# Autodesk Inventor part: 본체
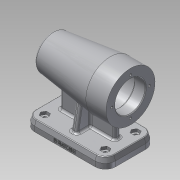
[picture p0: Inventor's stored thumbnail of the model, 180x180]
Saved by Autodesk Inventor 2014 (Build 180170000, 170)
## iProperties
Created: 2017-01
Part Number: 본체
Material: 알루미늄 6061
Document SubType Name: Modeling
Designer: Administrator
Mass: 795.171 g
Surface Area: 661.82 cm^2
Volume: 293.421 cm^3
Density: 2.71 g/cm^3
Appearance: 알루미늄 - 평지
Author: Administrator
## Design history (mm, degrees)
sketch "스케치1"
  geometry: L1 (-56, 35)-(56, 35); L2 (56, 35)-(56, -35); L3 (56, -35)-(-56, -35); L4 (-56, -35)-(-56, 35); L5 (-56, 35)-(56, -35); L6 (56, 35)-(-56, -35); 1 further point
  constraints: 12 end point, 2 midpoint, 2 parallel, 1 horizontal, 1 perpendicular
  dimensions: "d0" = 70 distance of L1.end L2.end; "d1" = 112 distance of L1.start L1.end
extrude "돌출1" new body sketch "스케치1" distance "d2" = 14; taper "d3" = 0 deg
fillet "모깎기1" dims "d4" = 14
chamfer "모따기1" distance "d5" = 7; stored, may be unused: second distance "d6" = 2, angle "d7" = 15 deg
fillet "모깎기2" dims "d8" = 1
sketch "스케치2"
  geometry: L1 (-38, 4)-(38, 4); L2 (38, 4)-(38, -4); L3 (38, -4)-(-38, -4); L4 (-38, -4)-(-38, 4); L5 (-38, 4)-(38, -4); L6 (38, 4)-(-38, -4); L7 (56, 21)-(56, -21) reference; L8 (-56, 21)-(-56, -21) reference; L9 (-4, 23)-(4, 23); L10 (4, 23)-(4, -23); L11 (4, -23)-(-4, -23); L12 (-4, -23)-(-4, 23); L13 (-4, 23)-(4, -23); L14 (4, 23)-(-4, -23); 1 further point
  constraints: 24 end point, 4 midpoint, 4 parallel, 2 horizontal, 2 perpendicular
  dimensions: "d9" = 76 distance of L1.start L1.end; "d12" = 8 distance of L3.end L1.start; "d13" = 8 distance of L9.start L9.end; "d14" = 46 distance of L9.end L10.end
extrude "돌출2" join sketch "스케치2" distance "d15" = 74; taper "d16" = 0 deg
feature "면 기울기1" dims angle "d17" = 10 deg
sketch "스케치3"
  geometry: L1 (56, 74)-(-56, 74); L2 (56, 74)-(56, 108); L3 (56, 108)-(28, 108); L4 (28, 108)-(-52.27, 98.144); L5 (42, 0)-(-42, 0) reference; A1 r 80 centre (24, 74) between (-52.27, 98.144) and (-56, 74); 3 further points
  constraints: 8 end point, 2 midpoint, 2 perpendicular, 2 point on circle, 1 centre point, 1 horizontal, 1 horizontal alignment, 1 vertical alignment
  dimensions: "d18" = 28 distance of L2.end L3.end; "d19" = 80 radius of A1; "d20" = 112 distance of L1.start L1.end; "d21" = 7 deg angle of L3 L4; "d22" = 74 distance between parallel lines of L5 L1; "d23" = 68 diameter of L3 L1
revolve "회전1" sketch "스케치3" stored, may be unused: angle "d24" = 90 deg
sketch "스케치4"
  geometry: L1 (56, 40)-(56, 108) reference; L2 (56, 74)-(41, 74); L3 (41, 74)-(41, 95); L4 (41, 95)-(56, 95); L5 (56, 95)-(56, 74); L6 (41, 74)-(-13, 74); L7 (-13, 74)-(-13, 98); L8 (-13, 98)-(41, 98); L9 (41, 98)-(41, 74); L10 (-13, 74)-(-25, 74); L11 (-25, 74)-(-25, 95); L12 (-25, 95)-(-13, 95); L13 (-13, 95)-(-13, 74); L14 (-25, 74)-(-43, 74); L15 (-43, 74)-(-43, 91.5); L16 (-43, 91.5)-(-25, 91.5); L17 (-25, 91.5)-(-25, 74); L18 (-43, 74)-(-47, 74); L19 (-47, 74)-(-47, 90); L20 (-47, 90)-(-43, 90); L21 (-43, 90)-(-43, 74); L22 (-47, 74)-(-50, 74); L23 (-50, 74)-(-50, 84.5); L24 (-50, 84.5)-(-47, 84.5); L25 (-47, 84.5)-(-47, 74); A1 r 80 centre (24, 74) between (-52.27, 98.144) and (-52.27, 49.856) reference; 1 further point
  constraints: 48 end point, 12 parallel, 6 horizontal, 6 perpendicular, 1 midpoint
  dimensions: "d25" = 15 distance of L3.end L4.end; "d26" = 54 distance of L7.end L8.end; "d27" = 12 distance of L11.end L12.end; "d28" = 18 distance of L15.end L16.end; "d29" = 4 distance of L19.end L20.end; "d30" = 3 distance of L23.end L24.end; "d31" = 42 diameter of L4 L2; "d32" = 48 diameter of L8 L6; "d33" = 42 diameter of L12 L10; "d34" = 35 diameter of L16 L14; "d35" = 32 diameter of L20 L18; "d36" = 21 diameter of L24 L22
revolve "회전2" sketch "스케치4" stored, may be unused: angle "d37" = 90 deg
fillet "모깎기3" dims "d38" = 3
fillet "모깎기4" dims "d39" = 0.3
fillet "모깎기5" dims "d40" = 3
chamfer "모따기2" distance "d41" = 1; stored, may be unused: second distance "d42" = 2, angle "d43" = 15 deg
fillet "모깎기6" dims "d44" = 3
fillet "모깎기7" dims "d45" = 3, "d46" = 3
sketch "스케치6"
  geometry: C1 r 22 at (0, 0) reference; A1 r 26 centre (0, 0) between (26, 0) and (0, 26); 3 further points
  constraints: 4 point on circle, 1 centre point
  dimensions: "d47" = 52 diameter of A1
hole "구멍1" sketch "스케치6" at (26, 0), (0, 26), (0, -26), (-26, 0) diameter "d48" = 3.242; stored, may be unused: countersink angle "d52" = 90 deg, drill point angle "d54" = 118 deg; dims "d49" = 8, "d50" = 4, "d51" = 2, "d53" = 11
fillet "모깎기8" dims "d55" = 3
sketch "스케치7"
  geometry: L1 (-42, 21)-(42, 21); L2 (42, 21)-(42, -21); L3 (42, -21)-(-42, -21); L4 (-42, -21)-(-42, 21); L5 (-42, 21)-(42, -21); L6 (42, 21)-(-42, -21); L7 (-39.113, 26)-(-36.226, 21); L8 (-36.226, 21)-(-39.113, 16); L9 (-39.113, 16)-(-44.887, 16); L10 (-44.887, 16)-(-47.774, 21); L11 (-47.774, 21)-(-44.887, 26); L12 (-44.887, 26)-(-39.113, 26); L13 (-39.113, -16)-(-36.226, -21); L14 (-36.226, -21)-(-39.113, -26); L15 (-39.113, -26)-(-44.887, -26); L16 (-44.887, -26)-(-47.774, -21); L17 (-47.774, -21)-(-44.887, -16); L18 (-44.887, -16)-(-39.113, -16); L19 (44.887, 26)-(47.774, 21); L20 (47.774, 21)-(44.887, 16); L21 (44.887, 16)-(39.113, 16); L22 (39.113, 16)-(36.226, 21); L23 (36.226, 21)-(39.113, 26); L24 (39.113, 26)-(44.887, 26); L25 (44.887, -16)-(47.774, -21); L26 (47.774, -21)-(44.887, -26); L27 (44.887, -26)-(39.113, -26); L28 (39.113, -26)-(36.226, -21); L29 (36.226, -21)-(39.113, -16); L30 (39.113, -16)-(44.887, -16); 13 further points
  constraints: 60 end point, 6 midpoint, 4 coincident, 2 parallel, 1 horizontal, 1 perpendicular, 1 point on line, 52 other
  dimensions: "d56" = 42 distance of L1.end L2.end; "d57" = 84 distance of L1.start L1.end
extrude "돌출3" cut sketch "스케치7" distance "d62" = 4; taper "d63" = 0 deg
sketch "스케치8"
  geometry: L1 (-42, -21)-(42, -21); L2 (42, -21)-(42, 21); L3 (42, 21)-(-42, 21); L4 (-42, 21)-(-42, -21); L5 (-42, -21)-(42, 21); L6 (42, -21)-(-42, 21); A1 r 11.357 centre (42, 21) between (53.357, 21) and (42, 32.357) reference; 5 further points
  constraints: 12 end point, 4 coincident, 2 midpoint, 2 parallel, 1 horizontal, 1 perpendicular
hole "구멍2" sketch "스케치8" at (-42, 21), (42, 21), (42, -21), (-42, -21) diameter "d64" = 5; stored, may be unused: countersink angle "d68" = 90 deg, drill point angle "d70" = 118 deg; dims "d65" = 8, "d66" = 4, "d67" = 2, "d69" = 11
node "작업 평면1"
sketch "스케치9"
  geometry: L1 (56, 0)-(56, 7) reference; L2 (42, 0)-(-42, 0) reference; 2 further points
  constraints: 1 other
  dimensions: "d72" = 56 distance from line of L1 point (0, 4); "d73" = 4 distance from line of point (0, 4) L2
feature "엠보싱1" sketch "스케치9" dims "d0" = 70, "d1" = 112, "d8" = 1, "d74" = 0.5, "d75" = 0
sketch "스케치10"
  geometry: 1 further point
node "솔리드1"
other parameters: "d71" = 47.25
